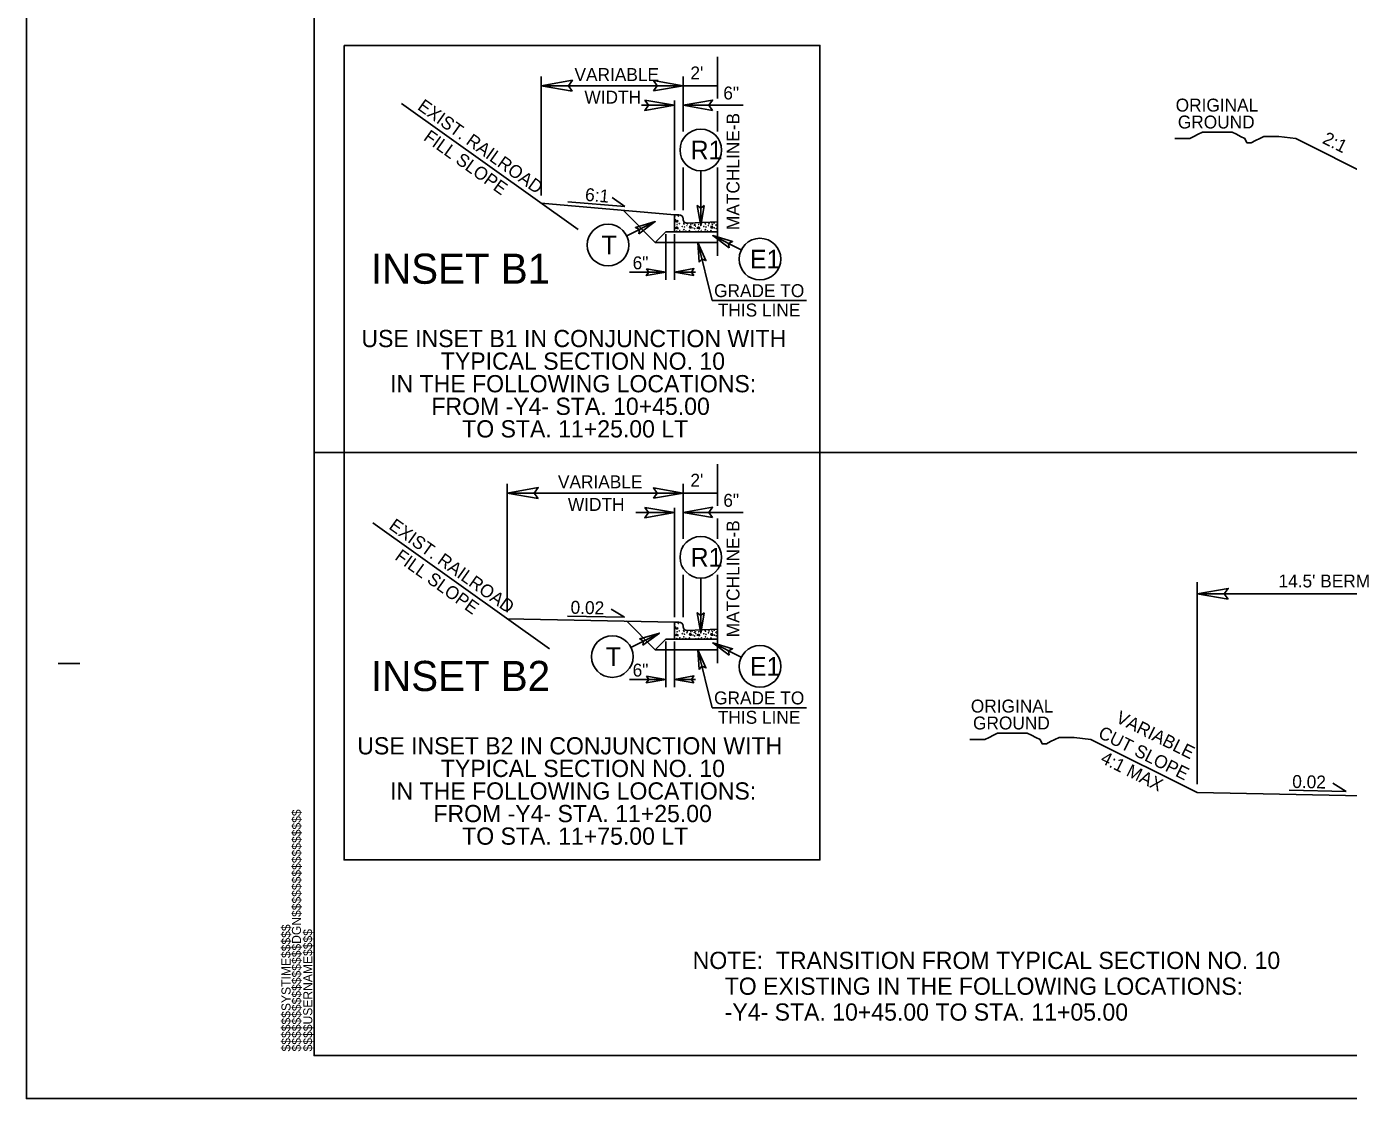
# Model space of a CAD drawing. Extents: x 1487909 to 1489267, y 497866 to 499814.
# Drawn here: x 1488883.3 to 1488960, y 497986.7 to 498048.9 of the extents above; entities that cross this region are included whole.
import ezdxf

# ---------------------------------------------------------------- set-up
doc = ezdxf.new("R2010")
doc.units = 0
for name, color, linetype in [('Exist XS Ground Line', 7, 'Continuous'), ('Prop Dimension', 7, 'Continuous'), ('Prop Dimension Text', 7, 'Continuous'), ('Prop Terminator CELL', 7, 'Continuous'), ('Scratch_Level_1', 7, 'Continuous'), ('Sheet Plot Border Outside CELL', 7, 'Continuous'), ('Sheet Typical CELL', 7, 'Continuous'), ('Typical Curb CELL', 7, 'Continuous'), ('Typical Hinge Slope Arterial CELL', 7, 'Continuous'), ('Typical ID Circle CELL', 7, 'Continuous'), ('Typical Pavement Slope CELL', 7, 'Continuous'), ('Typical Pavement Slope Information CELL', 7, 'Continuous'), ('Typical Terminator CELL', 7, 'Continuous'), ('Typical Text ID Circle CELL', 7, 'Continuous')]:
    doc.layers.add(name, color=color, linetype=linetype)

msp = doc.modelspace()

# ---------------------------------------------------------------- linework, layer by layer
at = {"layer": 'Exist XS Ground Line'}
for p, q in [((1488905.031, 498044.435), (1488915.282, 498037.11)), ((1488903.368, 498020.083), (1488913.619, 498012.758))]:
    msp.add_line(p, q, dxfattribs=at)
at = {"layer": 'Prop Dimension'}
for p, q in [((1488923.378, 498044.712), (1488923.378, 498047.141)), ((1488913.149, 498039.09), (1488913.149, 498045.989)), ((1488921.378, 498042.791), (1488921.378, 498045.989)), ((1488913.149, 498045.452), (1488921.378, 498045.452)), ((1488921.378, 498045.452), (1488923.378, 498045.452)), ((1488918.967, 498044.324), (1488920.878, 498044.324)), ((1488920.878, 498038.241), (1488920.878, 498044.602)), ((1488924.873, 498044.324), (1488921.378, 498044.324)), ((1488923.378, 498042.791), (1488923.378, 498043.978)), ((1488921.378, 498038.241), (1488921.378, 498040.711)), ((1488923.378, 498035.575), (1488923.378, 498040.711)), ((1488920.379, 498034.18), (1488920.379, 498036.834)), ((1488920.879, 498034.18), (1488920.879, 498036.834)), ((1488923.074, 498032.99), (1488922.241, 498036.354)), ((1488918.275, 498034.64), (1488920.379, 498034.64)), ((1488920.879, 498034.64), (1488922.101, 498034.64)), ((1488923.074, 498032.99), (1488928.547, 498032.99)), ((1488923.378, 498021.066), (1488923.378, 498023.495)), ((1488911.16, 498014.901), (1488911.16, 498022.343)), ((1488921.378, 498019.145), (1488921.378, 498022.343)), ((1488911.16, 498021.806), (1488921.378, 498021.806)), ((1488921.378, 498021.806), (1488923.378, 498021.806)), ((1488918.642, 498020.678), (1488920.878, 498020.678)), ((1488920.878, 498014.595), (1488920.878, 498020.956)), ((1488924.873, 498020.678), (1488921.378, 498020.678)), ((1488923.378, 498019.145), (1488923.378, 498020.332)), ((1488921.378, 498014.595), (1488921.378, 498017.065)), ((1488923.378, 498011.929), (1488923.378, 498017.065)), ((1488951.214, 498004.902), (1488951.214, 498016.638)), ((1488951.214, 498015.957), (1488965.714, 498015.957)), ((1488920.379, 498010.534), (1488920.379, 498013.188)), ((1488920.879, 498010.534), (1488920.879, 498013.188)), ((1488923.074, 498009.344), (1488922.241, 498012.708)), ((1488918.275, 498010.994), (1488920.379, 498010.994)), ((1488920.879, 498010.994), (1488922.101, 498010.994)), ((1488923.074, 498009.344), (1488928.547, 498009.344))]:
    msp.add_line(p, q, dxfattribs=at)
at = {"layer": 'Prop Terminator CELL'}
for points in [[(1488914.949, 498045.142), (1488913.149, 498045.452), (1488914.959, 498045.772), (1488914.729, 498045.452)], [(1488919.668, 498045.157), (1488921.378, 498045.452), (1488919.658, 498045.756), (1488919.877, 498045.452)], [(1488919.168, 498044.618), (1488920.878, 498044.324), (1488919.159, 498044.02), (1488919.377, 498044.324)], [(1488923.088, 498044.029), (1488921.378, 498044.324), (1488923.098, 498044.628), (1488922.879, 498044.324)], [(1488922.323, 498035.215), (1488922.241, 498036.354), (1488922.707, 498035.304), (1488922.478, 498035.395)], [(1488919.254, 498034.833), (1488920.379, 498034.64), (1488919.247, 498034.44), (1488919.391, 498034.64)], [(1488922.004, 498034.446), (1488920.879, 498034.64), (1488922.01, 498034.84), (1488921.866, 498034.64)], [(1488912.96, 498021.496), (1488911.16, 498021.806), (1488912.97, 498022.126), (1488912.74, 498021.806)], [(1488919.668, 498021.511), (1488921.378, 498021.806), (1488919.658, 498022.11), (1488919.877, 498021.806)], [(1488919.168, 498020.972), (1488920.878, 498020.678), (1488919.159, 498020.374), (1488919.377, 498020.678)], [(1488923.088, 498020.383), (1488921.378, 498020.678), (1488923.098, 498020.982), (1488922.879, 498020.678)], [(1488953.014, 498015.647), (1488951.214, 498015.957), (1488953.024, 498016.277), (1488952.794, 498015.957)], [(1488922.323, 498011.569), (1488922.241, 498012.708), (1488922.707, 498011.658), (1488922.478, 498011.749)], [(1488919.254, 498011.187), (1488920.379, 498010.994), (1488919.247, 498010.794), (1488919.391, 498010.994)], [(1488922.004, 498010.8), (1488920.879, 498010.994), (1488922.01, 498011.194), (1488921.866, 498010.994)]]:
    msp.add_lwpolyline(points, close=True, dxfattribs=at)
at = {"layer": 'Scratch_Level_1'}
msp.add_line((1488899.964, 498024.154), (1489049.964, 498024.154), dxfattribs=at)
at = {"layer": 'Sheet Plot Border Outside CELL'}
msp.add_lwpolyline([(1489051.664, 498096.654), (1488883.264, 498096.654), (1488883.264, 497986.654), (1489051.664, 497986.654)], close=True, dxfattribs=at)
at = {"layer": 'Sheet Typical CELL'}
for p, q in [((1488885.114, 498011.904), (1488886.364, 498011.904)), ((1488899.964, 497989.154), (1488899.964, 497989.154)), ((1488899.964, 497989.154), (1488899.964, 497989.154)), ((1488899.964, 497989.154), (1488899.964, 497989.154)), ((1488899.964, 497989.154), (1488899.964, 497989.154)), ((1488899.964, 497989.154), (1488899.964, 497989.154)), ((1488899.964, 497989.154), (1488899.964, 497989.154))]:
    msp.add_line(p, q, dxfattribs=at)
for points in [[(1489049.964, 498094.154), (1488899.964, 498094.154), (1488899.964, 497989.154), (1489049.964, 497989.154)], [(1488901.701, 498047.8), (1488929.328, 498047.8), (1488929.328, 498024.154), (1488901.701, 498024.154)], [(1488901.701, 498024.154), (1488929.328, 498024.154), (1488929.328, 498000.508), (1488901.701, 498000.508)]]:
    msp.add_lwpolyline(points, close=True, dxfattribs=at)
at = {"layer": 'Typical Curb CELL'}
for p, q in [((1488920.879, 498036.967), (1488920.879, 498037.967)), ((1488920.879, 498037.967), (1488921.139, 498037.967)), ((1488920.915, 498037.589), (1488921.069, 498037.634)), ((1488921.052, 498037.543), (1488920.915, 498037.589)), ((1488921.041, 498037.27), (1488920.938, 498037.195)), ((1488920.938, 498037.195), (1488921.104, 498037.156)), ((1488921.104, 498037.156), (1488921.041, 498037.27)), ((1488921.069, 498037.634), (1488921.052, 498037.543)), ((1488921.378, 498037.717), (1488921.378, 498037.727)), ((1488923.378, 498037.55), (1488921.628, 498037.477)), ((1488921.783, 498037.326), (1488921.748, 498037.213)), ((1488921.748, 498037.213), (1488921.868, 498037.207)), ((1488921.868, 498037.207), (1488921.783, 498037.326)), ((1488922.29, 498037.27), (1488922.187, 498037.195)), ((1488922.187, 498037.195), (1488922.352, 498037.156)), ((1488922.352, 498037.156), (1488922.29, 498037.27)), ((1488923.031, 498037.326), (1488922.997, 498037.213)), ((1488922.997, 498037.213), (1488923.118, 498037.207)), ((1488923.118, 498037.207), (1488923.031, 498037.326)), ((1488923.378, 498036.967), (1488923.378, 498037.55)), ((1488920.879, 498036.967), (1488923.378, 498036.967)), ((1488920.879, 498013.321), (1488920.879, 498014.321)), ((1488920.879, 498014.321), (1488921.139, 498014.321)), ((1488920.915, 498013.943), (1488921.069, 498013.988)), ((1488921.052, 498013.897), (1488920.915, 498013.943)), ((1488921.041, 498013.624), (1488920.938, 498013.549)), ((1488920.938, 498013.549), (1488921.104, 498013.51)), ((1488921.104, 498013.51), (1488921.041, 498013.624)), ((1488921.069, 498013.988), (1488921.052, 498013.897)), ((1488921.378, 498014.071), (1488921.378, 498014.081)), ((1488923.378, 498013.904), (1488921.628, 498013.831)), ((1488921.783, 498013.68), (1488921.748, 498013.567)), ((1488921.748, 498013.567), (1488921.868, 498013.561)), ((1488921.868, 498013.561), (1488921.783, 498013.68)), ((1488922.29, 498013.624), (1488922.187, 498013.549)), ((1488922.187, 498013.549), (1488922.352, 498013.51)), ((1488922.352, 498013.51), (1488922.29, 498013.624)), ((1488923.031, 498013.68), (1488922.997, 498013.567)), ((1488922.997, 498013.567), (1488923.118, 498013.561)), ((1488923.118, 498013.561), (1488923.031, 498013.68)), ((1488923.378, 498013.321), (1488923.378, 498013.904)), ((1488920.879, 498013.321), (1488923.378, 498013.321))]:
    msp.add_line(p, q, dxfattribs=at)
for centre in [(1488920.892, 498037.857), (1488920.943, 498037.674), (1488921.04, 498037.401), (1488921.109, 498037.891), (1488921.16, 498037.452), (1488921.337, 498037.287), (1488921.417, 498037.48), (1488921.434, 498037.43), (1488921.463, 498037.258), (1488921.611, 498037.344), (1488921.64, 498037.446), (1488921.834, 498037.407), (1488921.931, 498037.461), (1488921.959, 498037.207), (1488922.039, 498037.367), (1488922.056, 498037.161), (1488922.095, 498037.401), (1488922.113, 498037.304), (1488922.289, 498037.401), (1488922.409, 498037.452), (1488922.586, 498037.287), (1488922.666, 498037.48), (1488922.683, 498037.43), (1488922.712, 498037.258), (1488922.86, 498037.344), (1488922.889, 498037.446), (1488923.037, 498037.509), (1488923.083, 498037.407), (1488923.18, 498037.492), (1488923.208, 498037.207), (1488923.289, 498037.367), (1488923.305, 498037.161), (1488923.345, 498037.401), (1488923.362, 498037.304), (1488921.023, 498037.013), (1488921.195, 498037.053), (1488921.371, 498036.99), (1488921.429, 498037.104), (1488921.543, 498037.019), (1488921.748, 498037.042), (1488921.908, 498036.973), (1488922.118, 498036.996), (1488922.272, 498037.013), (1488922.444, 498037.053), (1488922.621, 498036.99), (1488922.678, 498037.104), (1488922.792, 498037.019), (1488922.997, 498037.042), (1488923.157, 498036.973), (1488923.367, 498036.996), (1488920.892, 498014.211), (1488921.109, 498014.245), (1488920.943, 498014.028), (1488921.023, 498013.367), (1488921.04, 498013.755), (1488921.16, 498013.806), (1488921.195, 498013.407), (1488921.337, 498013.641), (1488921.417, 498013.834), (1488921.429, 498013.458), (1488921.434, 498013.784), (1488921.463, 498013.612), (1488921.543, 498013.373), (1488921.611, 498013.698), (1488921.64, 498013.8), (1488921.748, 498013.396), (1488921.834, 498013.761), (1488921.931, 498013.815), (1488921.959, 498013.561), (1488922.039, 498013.721), (1488922.056, 498013.515), (1488922.095, 498013.755), (1488922.113, 498013.658), (1488922.272, 498013.367), (1488922.289, 498013.755), (1488922.409, 498013.806), (1488922.444, 498013.407), (1488922.586, 498013.641), (1488922.666, 498013.834), (1488922.678, 498013.458), (1488922.683, 498013.784), (1488922.712, 498013.612), (1488922.792, 498013.373), (1488922.86, 498013.698), (1488922.889, 498013.8), (1488922.997, 498013.396), (1488923.037, 498013.863), (1488923.083, 498013.761), (1488923.18, 498013.846), (1488923.208, 498013.561), (1488923.289, 498013.721), (1488923.305, 498013.515), (1488923.345, 498013.755), (1488923.362, 498013.658), (1488921.371, 498013.344), (1488921.908, 498013.327), (1488922.118, 498013.35), (1488922.621, 498013.344), (1488923.157, 498013.327), (1488923.367, 498013.35)]:
    msp.add_circle(centre, 0.00802, dxfattribs=at)
for centre, start, end in [((1488921.139, 498037.727), 0, 90), ((1488921.618, 498037.717), 180, 272.38446), ((1488921.139, 498014.081), 0, 90), ((1488921.618, 498014.071), 180, 272.38446)]:
    msp.add_arc(centre, 0.24, start, end, dxfattribs=at)
at = {"layer": 'Typical Hinge Slope Arterial CELL'}
for p, q in [((1488956.949, 498042.394), (1488961.464, 498040.137)), ((1488945.059, 498007.503), (1488951.214, 498004.426))]:
    msp.add_line(p, q, dxfattribs=at)
for points in [[(1488956.949, 498042.394), (1488955.964, 498042.517), (1488955.717, 498042.517), (1488955.347, 498042.517), (1488955.101, 498042.517), (1488954.854, 498042.394), (1488954.608, 498042.271), (1488954.362, 498042.147), (1488954.115, 498042.147), (1488953.992, 498042.394), (1488953.745, 498042.517), (1488953.499, 498042.641), (1488953.253, 498042.763), (1488953.006, 498042.763), (1488952.76, 498042.763), (1488952.513, 498042.763), (1488952.267, 498042.763), (1488952.021, 498042.763), (1488951.774, 498042.763), (1488951.528, 498042.763), (1488951.282, 498042.641), (1488951.035, 498042.517), (1488950.789, 498042.394), (1488950.419, 498042.394), (1488950.172, 498042.394), (1488949.926, 498042.394)], [(1488945.059, 498007.503), (1488944.074, 498007.626), (1488943.827, 498007.626), (1488943.457, 498007.626), (1488943.211, 498007.626), (1488942.964, 498007.503), (1488942.718, 498007.379), (1488942.472, 498007.256), (1488942.225, 498007.256), (1488942.102, 498007.503), (1488941.855, 498007.626), (1488941.609, 498007.749), (1488941.363, 498007.872), (1488941.116, 498007.872), (1488940.87, 498007.872), (1488940.623, 498007.872), (1488940.377, 498007.872), (1488940.131, 498007.872), (1488939.884, 498007.872), (1488939.638, 498007.872), (1488939.392, 498007.749), (1488939.145, 498007.626), (1488938.899, 498007.503), (1488938.529, 498007.503), (1488938.283, 498007.503), (1488938.036, 498007.503)]]:
    msp.add_lwpolyline(points, dxfattribs=at)
at = {"layer": 'Typical ID Circle CELL'}
for p, q in [((1488922.41, 498040.517), (1488922.41, 498037.324)), ((1488918.107, 498036.746), (1488919.765, 498037.57)), ((1488924.762, 498035.93), (1488923.105, 498036.754)), ((1488922.41, 498016.871), (1488922.41, 498013.678)), ((1488918.353, 498012.851), (1488920.011, 498013.675)), ((1488924.762, 498012.284), (1488923.105, 498013.108))]:
    msp.add_line(p, q, dxfattribs=at)
for centre in [(1488922.41, 498041.726), (1488917.025, 498036.208), (1488925.844, 498035.392), (1488922.41, 498018.08), (1488917.271, 498012.313), (1488925.844, 498011.746)]:
    msp.add_circle(centre, 1.208, dxfattribs=at)
at = {"layer": 'Typical Pavement Slope CELL'}
for p, q in [((1488920.879, 498037.967), (1488913.149, 498038.634)), ((1488917.895, 498038.224), (1488919.765, 498036.354)), ((1488920.379, 498036.967), (1488919.765, 498036.354)), ((1488920.879, 498036.967), (1488920.379, 498036.967)), ((1488923.378, 498036.354), (1488919.765, 498036.354)), ((1488920.879, 498014.321), (1488911.16, 498014.515)), ((1488918.087, 498014.387), (1488919.765, 498012.708)), ((1488920.379, 498013.321), (1488919.765, 498012.708)), ((1488923.378, 498012.708), (1488919.765, 498012.708)), ((1488920.879, 498013.321), (1488920.379, 498013.321)), ((1488965.214, 498004.146), (1488951.214, 498004.426))]:
    msp.add_line(p, q, dxfattribs=at)
at = {"layer": 'Typical Pavement Slope Information CELL'}
for p, q in [((1488918.005, 498038.44), (1488914.7, 498038.725)), ((1488918.005, 498038.44), (1488917.255, 498038.964)), ((1488917.98, 498014.604), (1488917.197, 498015.077)), ((1488917.98, 498014.604), (1488914.663, 498014.67)), ((1488959.872, 498004.489), (1488959.089, 498004.962)), ((1488959.872, 498004.489), (1488956.556, 498004.555))]:
    msp.add_line(p, q, dxfattribs=at)
at = {"layer": 'Typical Terminator CELL'}
for points in [[(1488922.612, 498038.496), (1488922.41, 498037.324), (1488922.202, 498038.502), (1488922.41, 498038.353)], [(1488918.806, 498036.868), (1488919.765, 498037.57), (1488918.617, 498037.232), (1488918.844, 498037.112)], [(1488924.064, 498036.052), (1488923.105, 498036.754), (1488924.253, 498036.416), (1488924.026, 498036.296)], [(1488922.612, 498014.85), (1488922.41, 498013.678), (1488922.202, 498014.856), (1488922.41, 498014.707)], [(1488919.052, 498012.972), (1488920.011, 498013.675), (1488918.863, 498013.337), (1488919.09, 498013.217)], [(1488924.064, 498012.406), (1488923.105, 498013.108), (1488924.253, 498012.77), (1488924.026, 498012.65)]]:
    msp.add_lwpolyline(points, close=True, dxfattribs=at)

# ---------------------------------------------------------------- texts
at = {"layer": 'Prop Dimension Text'}
for s, p in [('VARIABLE', (1488915.077, 498045.733)), ("2'", (1488921.806, 498045.825)), ('WIDTH', (1488915.654, 498044.42)), ('6"', (1488923.716, 498044.66)), ('6"', (1488918.452, 498034.801)), ('GRADE TO', (1488923.18, 498033.185)), ('THIS LINE', (1488923.399, 498032.06)), ('VARIABLE', (1488914.117, 498022.087)), ("2'", (1488921.806, 498022.179)), ('WIDTH', (1488914.695, 498020.774)), ('6"', (1488923.716, 498021.014)), ("14.5' BERM", (1488955.945, 498016.33)), ('6"', (1488918.452, 498011.155)), ('GRADE TO', (1488923.18, 498009.539)), ('THIS LINE', (1488923.399, 498008.414))]:
    msp.add_text(s, height=0.75, dxfattribs=at).set_placement(p)
at = {"layer": 'Sheet Typical CELL'}
for s, p in [('$$$$$$$$$$$$$$$$DGN$$$$$$$$$$$$$$$$', (1488899.199, 497989.39)), ('$$$$$$SYSTIME$$$$$', (1488898.594, 497989.39)), ('$$$$USERNAME$$$$', (1488899.856, 497989.392))]:
    msp.add_text(s, height=0.525, rotation=90, dxfattribs=at).set_placement(p)
at = {"layer": 'Typical Hinge Slope Arterial CELL'}
for s, rotation, p in [('EXIST. RAILROAD', 324.48285, (1488905.912, 498044.123)), ('MATCHLINE-B', 90, (1488924.655, 498037.079)), ('FILL SLOPE', 324.48285, (1488906.259, 498042.339)), ('2:1', 333.46576, (1488958.44, 498042.149)), ('EXIST. RAILROAD', 324.48285, (1488904.249, 498019.771)), ('MATCHLINE-B', 90, (1488924.655, 498013.433)), ('FILL SLOPE', 324.48285, (1488904.596, 498017.988)), ('VARIABLE', 333.46576, (1488946.444, 498008.531)), ('CUT SLOPE', 333.46576, (1488945.418, 498007.646)), ('4:1 MAX', 333.46576, (1488945.556, 498006.18))]:
    msp.add_text(s, height=0.75, rotation=rotation, dxfattribs=at).set_placement(p)
for s, height, p in [('ORIGINAL', 0.75, (1488949.975, 498043.958)), ('GROUND', 0.75, (1488950.101, 498042.975)), ('USE INSET B1 IN CONJUNCTION WITH', 1, (1488902.708, 498030.281)), ('TYPICAL SECTION NO. 10', 1, (1488907.319, 498028.97)), ('IN THE FOLLOWING LOCATIONS:', 1, (1488904.376, 498027.659)), ('FROM -Y4- STA. 10+45.00', 1, (1488906.769, 498026.348)), ('TO STA. 11+25.00 LT', 1, (1488908.558, 498025.037)), ('ORIGINAL', 0.75, (1488938.085, 498009.067)), ('GROUND', 0.75, (1488938.211, 498008.084)), ('USE INSET B2 IN CONJUNCTION WITH', 1, (1488902.469, 498006.635)), ('TYPICAL SECTION NO. 10', 1, (1488907.319, 498005.324)), ('IN THE FOLLOWING LOCATIONS:', 1, (1488904.376, 498004.013)), ('FROM -Y4- STA. 11+25.00', 1, (1488906.888, 498002.702)), ('TO STA. 11+75.00 LT', 1, (1488908.558, 498001.391)), ('NOTE:  TRANSITION FROM TYPICAL SECTION NO. 10 ', 1, (1488921.939, 497994.178)), ('     TO EXISTING IN THE FOLLOWING LOCATIONS:', 1, (1488921.939, 497992.678)), ('     -Y4- STA. 10+45.00 TO STA. 11+05.00', 1, (1488921.939, 497991.178))]:
    msp.add_text(s, height=height, dxfattribs=at).set_placement(p)
at = {"layer": 'Typical Pavement Slope CELL'}
for s, p in [('INSET B1', (1488903.258, 498033.96)), ('INSET B2', (1488903.258, 498010.314))]:
    msp.add_text(s, height=1.75, dxfattribs=at).set_placement(p)
at = {"layer": 'Typical Pavement Slope Information CELL'}
for s, rotation, p in [('6:1', 355.06989, (1488915.668, 498038.781)), ('0.02', 358.85426, (1488914.844, 498014.805)), ('0.02', 358.85426, (1488956.736, 498004.69))]:
    msp.add_text(s, height=0.75, rotation=rotation, dxfattribs=at).set_placement(p)
at = {"layer": 'Typical Text ID Circle CELL'}
for s, height, p in [('R1', 1.0817, (1488921.817, 498041.185)), ('T', 1.082, (1488916.65, 498035.667)), ('E1', 1.0817, (1488925.259, 498034.851)), ('R1', 1.0817, (1488921.817, 498017.539)), ('T', 1.082, (1488916.896, 498011.772)), ('E1', 1.0817, (1488925.259, 498011.205))]:
    msp.add_text(s, height=height, dxfattribs=at).set_placement(p)

doc.saveas('drawing.dxf')
